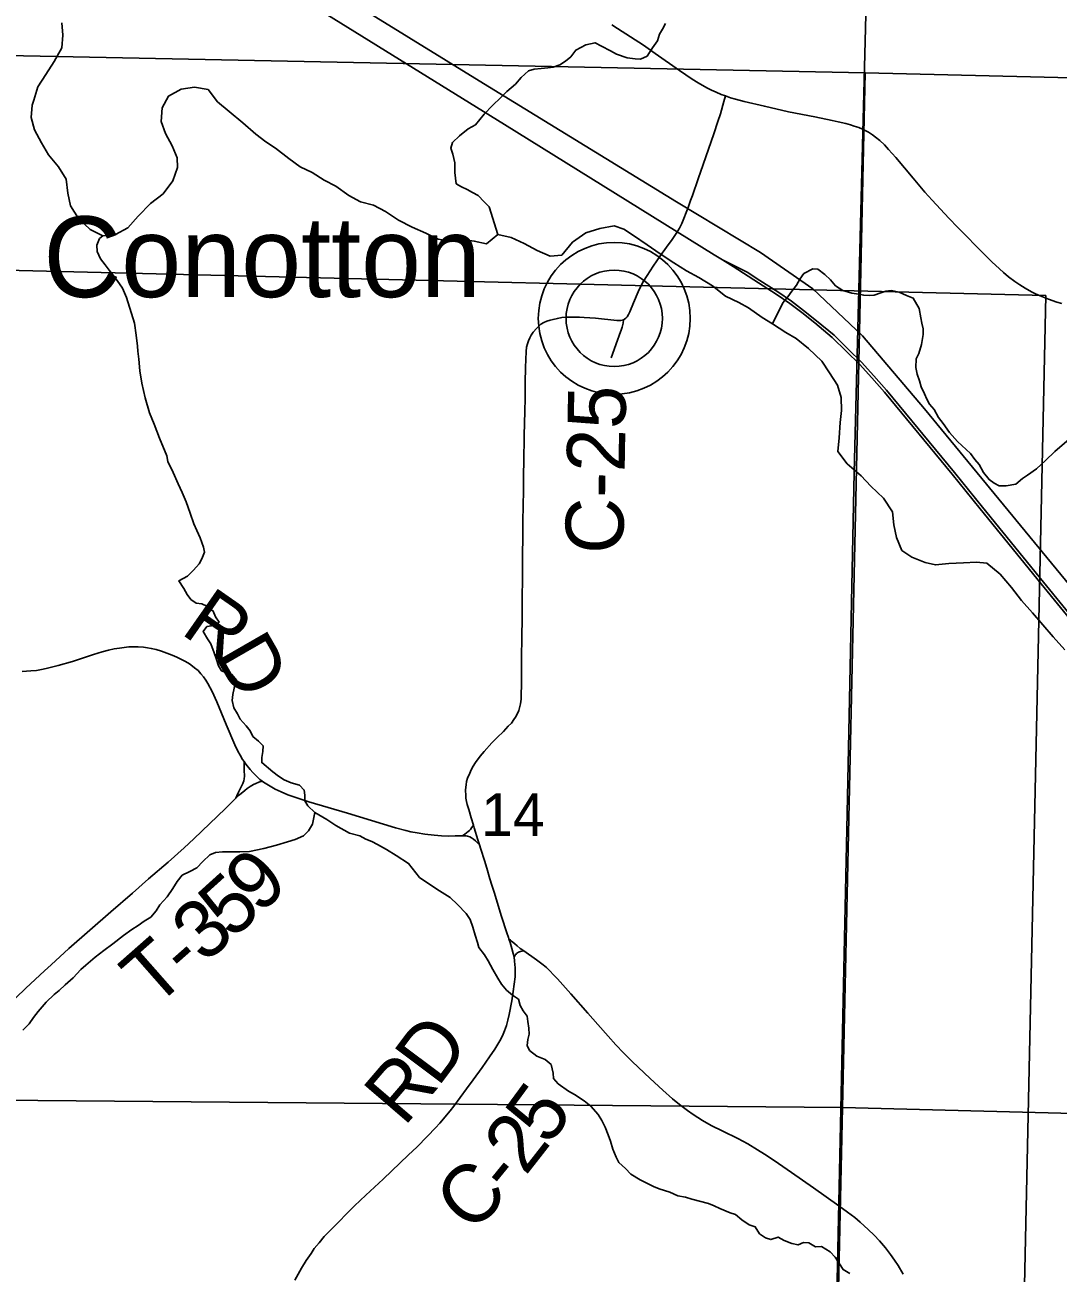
# Model space of a CAD drawing. Extents: x -19.9 to 41.9, y 0 to 32.3.
# Drawn here: x 7.065 to 8.077, y 15.733 to 16.956 of the extents above; entities that cross this region are included whole.
import ezdxf

# ---------------------------------------------------------------- set-up
doc = ezdxf.new("R2010")
doc.units = 0
for name, color, linetype in [('GM_X_Corporation', 7, 'Continuous'), ('GM_X_County_Road', 7, 'Continuous'), ('GM_X_County_Road_Text', 7, 'Continuous'), ('GM_X_Major_River', 7, 'Continuous'), ('GM_X_Minor_River', 7, 'Continuous'), ('GM_X_Rail_Line', 7, 'Continuous'), ('GM_X_Section', 7, 'Continuous'), ('GM_X_Section_Text', 7, 'Continuous'), ('GM_X_State_Route', 7, 'Continuous'), ('GM_X_Township_Road', 7, 'Continuous'), ('GM_X_Township_Road_Text', 7, 'Continuous'), ('GM_X_Unincorporated', 7, 'Continuous'), ('GM_X_Unincorporated_Location', 7, 'Continuous'), ('GM_X_Unincorporated_Text', 7, 'Continuous')]:
    doc.layers.add(name, color=color, linetype=linetype)

msp = doc.modelspace()

# ---------------------------------------------------------------- linework, layer by layer
at = {"layer": 'GM_X_Corporation'}
msp.add_lwpolyline([(2.1, 17.918), (2.1, 14.1), (7.8246, 14.1), (7.8518, 15.3043), (7.854, 15.4058), (7.8702, 16.1679), (7.8776, 16.5173), (7.9012, 17.4524), (7.9072, 17.9171)], dxfattribs=at)
for points in [[(7.8246, 14.1), (8.9, 14.1), (8.9, 17.8974), (7.9072, 17.9171), (7.9012, 17.4524), (7.8776, 16.5173), (7.8702, 16.1679), (7.854, 15.4058), (7.8518, 15.3043)], [(6.8696, 16.9292), (7.8883, 16.9088), (7.8659, 15.8953), (6.8522, 15.9041)], [(8.9, 16.5515), (8.9, 16.8843), (7.8883, 16.9088), (7.8659, 15.8953), (8.8854, 15.8688)], [(7.8659, 15.8953), (7.8436, 14.8739), (6.8226, 14.894), (6.8522, 15.9041)], [(8.8854, 15.8688), (8.8595, 14.8618), (7.8436, 14.8739), (7.8659, 15.8953)]]:
    msp.add_lwpolyline(points, close=True, dxfattribs=at)
at = {"layer": 'GM_X_County_Road'}
for points in [[(7.7173, 16.7836), (7.719, 16.7884), (7.7247, 16.8048), (7.7297, 16.8188), (7.74, 16.8488), (7.7441, 16.861), (7.7466, 16.8685), (7.7498, 16.8807), (7.7513, 16.886)], [(7.5105, 16.1524), (7.5089, 16.1575), (7.5054, 16.169), (7.5046, 16.1716), (7.5023, 16.179), (7.5, 16.1871), (7.4985, 16.1921), (7.4978, 16.1948), (7.4972, 16.1982), (7.4971, 16.2005), (7.4968, 16.2063), (7.4973, 16.2114), (7.4979, 16.2146), (7.4989, 16.2178), (7.5009, 16.2227), (7.5024, 16.2261), (7.5043, 16.2296), (7.5066, 16.2332), (7.511, 16.2392), (7.5152, 16.2438), (7.5226, 16.2524), (7.5278, 16.2575), (7.534, 16.2636), (7.5387, 16.2686), (7.5417, 16.2718), (7.5442, 16.2751), (7.5458, 16.2775), (7.5475, 16.2805), (7.549, 16.2841), (7.5497, 16.2866), (7.5507, 16.2907), (7.5512, 16.2953), (7.5514, 16.3011), (7.5516, 16.3078), (7.5517, 16.3378), (7.5519, 16.3537), (7.552, 16.3602), (7.5522, 16.3704), (7.5523, 16.381), (7.5524, 16.3921), (7.5525, 16.4157), (7.5526, 16.4238), (7.5527, 16.4358), (7.5529, 16.4544), (7.553, 16.467), (7.5533, 16.4873), (7.5535, 16.4969), (7.5537, 16.5158), (7.5538, 16.5273), (7.5542, 16.5536), (7.5548, 16.5772), (7.5551, 16.5896), (7.5553, 16.6055), (7.5556, 16.6199), (7.5561, 16.6357), (7.5566, 16.6401), (7.5575, 16.6433), (7.5585, 16.6463), (7.5597, 16.6491), (7.5612, 16.6516), (7.5632, 16.6546), (7.5662, 16.6582), (7.5682, 16.6603), (7.5707, 16.6624), (7.5736, 16.6641), (7.5764, 16.6654), (7.5796, 16.6663), (7.5826, 16.6672), (7.5868, 16.6682), (7.5911, 16.6689), (7.5961, 16.6695), (7.6086, 16.6693), (7.6131, 16.6691), (7.6241, 16.6683), (7.645, 16.666), (7.6491, 16.6661), (7.6515, 16.6668), (7.6525, 16.6674), (7.6537, 16.6683), (7.6551, 16.6697), (7.6565, 16.6719), (7.6579, 16.6746), (7.6614, 16.6833), (7.666, 16.6942), (7.669, 16.7005), (7.6713, 16.7047), (7.6747, 16.7103), (7.6777, 16.7149), (7.6806, 16.7193), (7.6879, 16.7297), (7.6936, 16.7378), (7.6992, 16.7453), (7.7032, 16.7512), (7.7064, 16.7564), (7.7088, 16.7611), (7.7108, 16.7659), (7.7153, 16.7779), (7.7173, 16.7836)], [(7.0624, 16.3223), (7.0667, 16.3225), (7.0712, 16.3228), (7.0766, 16.3233), (7.0814, 16.3242), (7.0861, 16.3253), (7.0978, 16.3281), (7.1119, 16.3321), (7.1324, 16.3388), (7.141, 16.3415), (7.1472, 16.3431), (7.1526, 16.3444), (7.158, 16.3452), (7.1625, 16.3459), (7.1672, 16.3463), (7.1718, 16.3466), (7.1762, 16.3464), (7.1815, 16.346), (7.1853, 16.3454), (7.189, 16.3449), (7.1937, 16.3437), (7.1991, 16.3421), (7.2044, 16.3402), (7.2096, 16.3383), (7.2141, 16.3363), (7.2181, 16.3343), (7.2225, 16.3322), (7.2265, 16.3298), (7.2295, 16.3276), (7.2315, 16.3259), (7.2348, 16.3231), (7.2376, 16.3201), (7.2401, 16.3171), (7.2424, 16.3138), (7.2444, 16.3105), (7.2487, 16.3026), (7.2532, 16.2927), (7.2625, 16.2705), (7.271, 16.2504), (7.2738, 16.2444), (7.276, 16.2402), (7.2785, 16.2361), (7.28, 16.2341), (7.2818, 16.2315), (7.2859, 16.2263), (7.2884, 16.2234), (7.292, 16.2196), (7.2954, 16.2166), (7.2976, 16.2149), (7.2988, 16.214), (7.3005, 16.2128), (7.3056, 16.2098), (7.3105, 16.2069), (7.3162, 16.2043), (7.3227, 16.2016), (7.3295, 16.1992), (7.3434, 16.1947), (7.3812, 16.1835), (7.4166, 16.1727), (7.4281, 16.1692), (7.4383, 16.1665), (7.4434, 16.1653), (7.4495, 16.1642), (7.457, 16.163), (7.4662, 16.1619), (7.4733, 16.1613), (7.4805, 16.1611), (7.4866, 16.1612), (7.4913, 16.1613), (7.4938, 16.1614)], [(7.4938, 16.1614), (7.4962, 16.163), (7.4979, 16.1642), (7.4994, 16.1654), (7.5008, 16.1666), (7.5016, 16.1675), (7.5028, 16.169), (7.504, 16.1707), (7.5046, 16.1716)], [(7.4938, 16.1614), (7.4975, 16.1612), (7.4989, 16.161), (7.501, 16.1603), (7.5027, 16.1595), (7.5047, 16.1582), (7.5065, 16.1565), (7.5085, 16.1545), (7.5105, 16.1524)], [(7.5392, 16.0604), (7.5388, 16.0616), (7.5372, 16.0663), (7.532, 16.0822), (7.5248, 16.106), (7.5225, 16.1131), (7.5207, 16.1192), (7.5176, 16.1297), (7.5153, 16.137), (7.5118, 16.1484), (7.5105, 16.1524)], [(7.3295, 15.7261), (7.3361, 15.7377), (7.3406, 15.7452), (7.3457, 15.7523), (7.3487, 15.757), (7.3535, 15.7628), (7.3585, 15.7687), (7.3646, 15.7752), (7.3721, 15.7827), (7.381, 15.7916), (7.3882, 15.7989), (7.3991, 15.8094), (7.416, 15.8251), (7.441, 15.8488), (7.4491, 15.8562), (7.4597, 15.867), (7.4674, 15.8752), (7.4716, 15.8798), (7.4818, 15.8921), (7.4853, 15.8966), (7.4979, 15.9135), (7.5044, 15.9224), (7.5131, 15.9344), (7.5204, 15.9448), (7.5256, 15.9525), (7.5296, 15.9589), (7.5313, 15.962), (7.5337, 15.967), (7.5351, 15.9704), (7.5369, 15.9754), (7.5384, 15.9806), (7.5397, 15.9864), (7.5422, 15.9998), (7.5436, 16.0088), (7.5455, 16.0233), (7.5456, 16.026), (7.5454, 16.0321), (7.5448, 16.0386), (7.5443, 16.0427), (7.5436, 16.0461), (7.5423, 16.0509), (7.5405, 16.0568), (7.5392, 16.0604)], [(7.5392, 16.0604), (7.5408, 16.0591), (7.542, 16.0581), (7.5433, 16.057), (7.545, 16.0556), (7.5473, 16.0537), (7.5505, 16.0511), (7.554, 16.0486), (7.5663, 16.04), (7.5691, 16.038), (7.5728, 16.0351), (7.5762, 16.0322), (7.5793, 16.0292), (7.5831, 16.0253), (7.5869, 16.0212), (7.5999, 16.0064), (7.6166, 15.9876), (7.6263, 15.9766), (7.6365, 15.965), (7.6441, 15.9566), (7.6514, 15.9488), (7.66, 15.9403), (7.6658, 15.9347), (7.6776, 15.9237), (7.6902, 15.9122), (7.6997, 15.9038), (7.7064, 15.8982), (7.7141, 15.8923), (7.7199, 15.8882), (7.7288, 15.8825), (7.7374, 15.8777), (7.749, 15.872), (7.7635, 15.8648), (7.7732, 15.8595), (7.7828, 15.8538), (7.7895, 15.8494), (7.7992, 15.8432), (7.816, 15.8315), (7.8377, 15.8165), (7.8625, 15.799), (7.8711, 15.7928), (7.8782, 15.7874), (7.8835, 15.7828), (7.8873, 15.7794), (7.8912, 15.7758), (7.897, 15.77), (7.9023, 15.7645), (7.9081, 15.7577), (7.9132, 15.7513), (7.9171, 15.7456), (7.9207, 15.7403), (7.9256, 15.7321)], [(7.5443, 16.0427), (7.5453, 16.0443), (7.546, 16.0452), (7.5468, 16.046), (7.5477, 16.0467), (7.5486, 16.0472), (7.5496, 16.0476), (7.5507, 16.048), (7.554, 16.0486)]]:
    msp.add_lwpolyline(points, dxfattribs=at)
at = {"layer": 'GM_X_Major_River'}
for points in [[(7.1014, 16.9578), (7.1023, 16.9457), (7.1013, 16.9332), (7.0939, 16.9198), (7.0857, 16.9072), (7.0779, 16.8949), (7.0739, 16.882)], [(7.0739, 16.882), (7.0724, 16.877), (7.0714, 16.8649), (7.0746, 16.8528), (7.0816, 16.84), (7.0882, 16.8283), (7.0982, 16.8166), (7.1055, 16.8046), (7.1072, 16.7909), (7.11, 16.7785), (7.1178, 16.766), (7.1293, 16.7552), (7.1415, 16.7489), (7.1541, 16.7502), (7.1661, 16.7568), (7.1762, 16.7683), (7.1882, 16.7806), (7.2007, 16.7902), (7.21, 16.8028), (7.2148, 16.8158), (7.2143, 16.8253), (7.2096, 16.8373), (7.203, 16.8494), (7.1987, 16.8611), (7.1996, 16.8744), (7.206, 16.8859), (7.2184, 16.8928), (7.2313, 16.8945), (7.2446, 16.8924), (7.2539, 16.8804), (7.2654, 16.8707), (7.2788, 16.8598), (7.2915, 16.8486), (7.3011, 16.8411), (7.3106, 16.8348), (7.3237, 16.8247), (7.3348, 16.8165), (7.3466, 16.8109), (7.3585, 16.8035), (7.3699, 16.7976), (7.3826, 16.7886), (7.394, 16.7823), (7.4066, 16.779), (7.4185, 16.7727), (7.4311, 16.7645), (7.4445, 16.7575), (7.4578, 16.7516), (7.4701, 16.7457), (7.4826, 16.7436), (7.4959, 16.7452), (7.5054, 16.7438), (7.5172, 16.7413), (7.5285, 16.7502), (7.5414, 16.7473), (7.5544, 16.7414), (7.567, 16.7347), (7.5796, 16.7292), (7.591, 16.7301), (7.6015, 16.7427), (7.6147, 16.752), (7.6283, 16.7563), (7.6423, 16.7588), (7.6518, 16.7555), (7.6614, 16.7492), (7.6748, 16.7402), (7.6874, 16.7313), (7.7008, 16.7227), (7.7131, 16.7149), (7.7253, 16.7082), (7.7387, 16.7), (7.7514, 16.6899), (7.7644, 16.6837), (7.7739, 16.6785), (7.7873, 16.6691), (7.7976, 16.6628), (7.8107, 16.6543), (7.8206, 16.6483), (7.8329, 16.6386), (7.8459, 16.6262), (7.8533, 16.6149), (7.861, 16.6029), (7.8646, 16.5908), (7.8651, 16.5779), (7.8638, 16.5661), (7.8628, 16.5513), (7.8615, 16.5377), (7.8707, 16.5256), (7.8842, 16.514), (7.8938, 16.5039), (7.9061, 16.4919), (7.915, 16.4788), (7.9163, 16.4659), (7.9191, 16.4534), (7.9242, 16.4409), (7.9341, 16.4342), (7.9471, 16.4291), (7.957, 16.4266), (7.9703, 16.4282), (7.9847, 16.4288), (7.9972, 16.4293), (8.0075, 16.4283)], [(8.0075, 16.4283), (8.0205, 16.4175), (8.0317, 16.4047), (8.0414, 16.3919), (8.0521, 16.3796), (8.0622, 16.3679), (8.0725, 16.3563), (8.0837, 16.3435)]]:
    msp.add_lwpolyline(points, dxfattribs=at)
at = {"layer": 'GM_X_Minor_River'}
for points in [[(7.5285, 16.7502), (7.52, 16.7773), (7.515, 16.7822), (7.5092, 16.7886), (7.5035, 16.7915), (7.4985, 16.7945), (7.4928, 16.7971), (7.4878, 16.8001), (7.4865, 16.8111), (7.4864, 16.8206), (7.4844, 16.8289), (7.4824, 16.835), (7.4842, 16.8404), (7.4909, 16.8469), (7.4995, 16.8539), (7.5067, 16.8578), (7.5152, 16.8683), (7.5231, 16.8767), (7.5313, 16.8845), (7.5373, 16.8903), (7.5459, 16.8977), (7.5514, 16.9042), (7.5585, 16.9108), (7.5642, 16.9124), (7.571, 16.9129), (7.5774, 16.9137), (7.5827, 16.9142), (7.5891, 16.9166), (7.5948, 16.9201), (7.6, 16.9244), (7.6048, 16.9309), (7.6146, 16.936), (7.6237, 16.9381), (7.6301, 16.9347), (7.6389, 16.9303), (7.6446, 16.927), (7.6553, 16.9233), (7.6629, 16.9223), (7.6682, 16.922), (7.6746, 16.9251), (7.6801, 16.9332), (7.685, 16.9401), (7.6868, 16.9466), (7.6897, 16.9516), (7.6927, 16.957)], [(7.1415, 16.7489), (7.1384, 16.7464), (7.1358, 16.7399), (7.1359, 16.7338), (7.1394, 16.7266), (7.1437, 16.7206), (7.1479, 16.7153), (7.1556, 16.7052), (7.1607, 16.6976), (7.1646, 16.6886), (7.1725, 16.6635), (7.1742, 16.6518), (7.1755, 16.6411), (7.1759, 16.6362), (7.1768, 16.6282), (7.1777, 16.6168), (7.1798, 16.6046), (7.183, 16.5902), (7.1874, 16.5758), (7.1917, 16.5645), (7.1972, 16.5508), (7.2043, 16.5334), (7.2051, 16.5281), (7.2106, 16.5172), (7.2153, 16.5062), (7.2192, 16.4975), (7.2231, 16.4884), (7.2271, 16.4774), (7.2306, 16.4668), (7.2338, 16.4604), (7.2369, 16.4532), (7.2401, 16.4441), (7.2413, 16.4392), (7.2387, 16.4327), (7.2358, 16.4277), (7.2305, 16.4215), (7.2246, 16.4157), (7.2159, 16.411), (7.221, 16.4035), (7.2241, 16.3978), (7.2279, 16.3929), (7.2329, 16.3892), (7.2386, 16.3885), (7.2435, 16.3863), (7.2497, 16.3815), (7.252, 16.3758), (7.2555, 16.3705), (7.2503, 16.3674), (7.2435, 16.3665), (7.2397, 16.3615), (7.244, 16.3543), (7.2475, 16.3495), (7.2506, 16.3407), (7.253, 16.3339), (7.255, 16.3279), (7.2577, 16.323), (7.2627, 16.3211), (7.268, 16.3193), (7.2726, 16.3137), (7.2701, 16.306), (7.269, 16.2999), (7.2684, 16.2938), (7.27, 16.2866), (7.2735, 16.2809), (7.2762, 16.2757), (7.282, 16.2689), (7.2858, 16.264), (7.2886, 16.2587), (7.2939, 16.2542), (7.2985, 16.2494), (7.2982, 16.244), (7.2972, 16.2379), (7.2973, 16.233), (7.308, 16.224), (7.3137, 16.2199), (7.3191, 16.2162), (7.3259, 16.2132), (7.3343, 16.2111), (7.3389, 16.2062), (7.3394, 16.2012), (7.3394, 16.1955), (7.3425, 16.1906), (7.3491, 16.1843), (7.3609, 16.1772), (7.3697, 16.1713), (7.3831, 16.1638), (7.3933, 16.1613), (7.3991, 16.158), (7.4051, 16.1558), (7.4105, 16.1528), (7.4193, 16.148), (7.4288, 16.1421), (7.441, 16.1343), (7.4519, 16.1204), (7.4599, 16.1148), (7.4714, 16.1073), (7.4817, 16.101), (7.489, 16.0939), (7.4974, 16.0853), (7.5013, 16.0792), (7.5041, 16.0717)], [(7.7976, 16.6628), (7.8075, 16.6835), (7.8124, 16.6893), (7.8165, 16.6947), (7.8209, 16.7008), (7.8242, 16.7066), (7.8283, 16.712), (7.837, 16.7167), (7.8419, 16.7164), (7.8488, 16.7111), (7.8542, 16.7059), (7.8592, 16.7002), (7.8664, 16.6954), (7.8752, 16.6929), (7.882, 16.6918), (7.8869, 16.6908), (7.8923, 16.6905), (7.8972, 16.6909), (7.9036, 16.6933), (7.9085, 16.6949), (7.9138, 16.6954), (7.9214, 16.694), (7.9286, 16.6906), (7.9354, 16.6881), (7.9413, 16.6779), (7.9429, 16.6688), (7.9438, 16.6635), (7.945, 16.6578), (7.9451, 16.6524), (7.9433, 16.6425), (7.9408, 16.6337), (7.9382, 16.6284), (7.9379, 16.62), (7.9392, 16.6135), (7.9415, 16.6071), (7.9431, 16.601), (7.9463, 16.5942), (7.9486, 16.5889), (7.9513, 16.584), (7.956, 16.5788), (7.9602, 16.5712), (7.9645, 16.5652), (7.971, 16.5565), (7.9788, 16.5475), (7.9914, 16.5359), (7.9957, 16.5299), (7.9999, 16.525), (8.0042, 16.5171), (8.0096, 16.5103), (8.0146, 16.5066), (8.0195, 16.504), (8.0263, 16.5041), (8.0358, 16.5057), (8.0425, 16.5112), (8.0474, 16.5147), (8.056, 16.5209), (8.065, 16.529), (8.0739, 16.5379), (8.0881, 16.5499)], [(7.3492, 16.1842), (7.347, 16.1728), (7.3429, 16.1663), (7.3381, 16.1613), (7.3298, 16.1577), (7.3226, 16.1553), (7.3117, 16.1521), (7.2992, 16.1489), (7.2853, 16.146), (7.2758, 16.1455), (7.2663, 16.1457), (7.2588, 16.1456), (7.252, 16.1451), (7.2463, 16.1427), (7.2396, 16.1362), (7.2336, 16.13), (7.2269, 16.1264), (7.2193, 16.1229), (7.2145, 16.1167), (7.2101, 16.1098), (7.2045, 16.1014), (7.1974, 16.0936), (7.1937, 16.0879), (7.1885, 16.0817), (7.1821, 16.0778), (7.1761, 16.0735), (7.1701, 16.0696), (7.1619, 16.0638), (7.1514, 16.0556), (7.1424, 16.049), (7.1342, 16.0424), (7.1248, 16.0347), (7.12, 16.0304), (7.1125, 16.0223), (7.1047, 16.0153), (7.0987, 16.0099), (7.0938, 16.006), (7.086, 15.9983), (7.0782, 15.9891), (7.0737, 15.9833), (7.0693, 15.9771), (7.0633, 15.9709)], [(7.5041, 16.0717), (7.5064, 16.0641), (7.5084, 16.0569), (7.51, 16.052), (7.5154, 16.0448), (7.5189, 16.0388), (7.5236, 16.0305), (7.5286, 16.0218), (7.5321, 16.0161), (7.5371, 16.0101), (7.5429, 16.0053), (7.5486, 16.0012), (7.5502, 15.9951), (7.5533, 15.9898), (7.5572, 15.9846), (7.558, 15.9796), (7.5589, 15.9728), (7.5593, 15.9671), (7.5579, 15.9617), (7.5572, 15.956), (7.5596, 15.9511), (7.5668, 15.9455), (7.5748, 15.9422), (7.5806, 15.9373), (7.5826, 15.929), (7.5831, 15.9237), (7.5877, 15.9184), (7.5976, 15.9113), (7.6037, 15.908), (7.6129, 15.9017), (7.6194, 15.8964), (7.6267, 15.8882), (7.6302, 15.8825), (7.6337, 15.8761), (7.6365, 15.8685), (7.6389, 15.8621), (7.6412, 15.8545), (7.6444, 15.8466), (7.6471, 15.8413), (7.6536, 15.8353), (7.6586, 15.83), (7.6678, 15.8245), (7.6808, 15.8178), (7.6865, 15.8156), (7.6968, 15.8124), (7.7048, 15.8087), (7.7124, 15.8073), (7.7184, 15.8055), (7.7348, 15.8011), (7.7405, 15.7989), (7.7458, 15.7964), (7.7561, 15.7919), (7.7614, 15.7905), (7.7676, 15.7853), (7.7745, 15.7804), (7.7806, 15.7782), (7.7848, 15.7715), (7.7905, 15.7677), (7.7959, 15.7659), (7.803, 15.7683), (7.8088, 15.765), (7.8164, 15.762), (7.8225, 15.7606), (7.8277, 15.763), (7.833, 15.7627), (7.8395, 15.7586), (7.8456, 15.7591), (7.854, 15.7539), (7.859, 15.7486), (7.8667, 15.7365), (7.8732, 15.7325)]]:
    msp.add_lwpolyline(points, dxfattribs=at)
at = {"layer": 'GM_X_Rail_Line'}
for points in [[(8.1483, 16.3345), (7.9464, 16.5797), (7.8856, 16.651), (7.837, 16.6972), (7.7859, 16.7327), (7.7034, 16.7822), (7.5103, 16.9007), (7.3078, 17.0259)], [(7.2854, 17.0128), (7.5349, 16.858), (7.7404, 16.7305), (7.7486, 16.7255), (7.7728, 16.7135), (7.7852, 16.7054), (7.8026, 16.6942), (7.8162, 16.6849), (7.8279, 16.676), (7.8406, 16.6659), (7.8579, 16.6516), (7.872, 16.6378), (7.8848, 16.6252), (7.8968, 16.6118), (7.9093, 16.5977), (7.9757, 16.5173), (8.0031, 16.4834), (8.0629, 16.4099), (8.1226, 16.3367)], [(7.7486, 16.7255), (7.7591, 16.7191), (7.7837, 16.703), (7.801, 16.6918), (7.8145, 16.6827), (7.8262, 16.6738), (7.8388, 16.6637), (7.856, 16.6495), (7.87, 16.6357), (7.8828, 16.6233), (7.8947, 16.6099), (7.9071, 16.5959), (7.9735, 16.5155), (8.0008, 16.4816), (8.0607, 16.4081), (8.1204, 16.3349)]]:
    msp.add_lwpolyline(points, dxfattribs=at)
at = {"layer": 'GM_X_Section'}
msp.add_lwpolyline([(8.0651, 16.6907), (8.0435, 15.6754), (7.0239, 15.7019), (7.0463, 16.7153)], close=True, dxfattribs=at)
at = {"layer": 'GM_X_State_Route'}
msp.add_lwpolyline([(7.6402, 16.9558), (7.6458, 16.9521), (7.6711, 16.9357), (7.6826, 16.9277), (7.7063, 16.9111), (7.7188, 16.9026), (7.7246, 16.8989), (7.7331, 16.894), (7.7376, 16.8917), (7.7422, 16.8896), (7.7471, 16.8876), (7.7513, 16.886), (7.7563, 16.8843), (7.7613, 16.8828), (7.7697, 16.8806), (7.7896, 16.8759), (7.8131, 16.8705), (7.8388, 16.8655), (7.8559, 16.8621), (7.8619, 16.8607), (7.8694, 16.859), (7.8738, 16.8578), (7.8776, 16.8566), (7.8819, 16.855), (7.8857, 16.8534), (7.8914, 16.8505), (7.8956, 16.8479), (7.8984, 16.8457), (7.9027, 16.8425), (7.9072, 16.8381), (7.9112, 16.8337), (7.9182, 16.8257), (7.9353, 16.8054), (7.9466, 16.7919), (7.9539, 16.7838), (7.9703, 16.7663), (7.9789, 16.7573), (8.0055, 16.7304), (8.0123, 16.7237), (8.0197, 16.7166), (8.0237, 16.7132), (8.0287, 16.709), (8.0348, 16.7044), (8.0398, 16.701), (8.0451, 16.6977), (8.0513, 16.6942), (8.0552, 16.6923), (8.0614, 16.6895), (8.0677, 16.687), (8.076, 16.6842), (8.0809, 16.6827)], dxfattribs=at)
at = {"layer": 'GM_X_Township_Road'}
for points in [[(7.6473, 16.6513), (7.6496, 16.6576), (7.6502, 16.6597), (7.6511, 16.6636), (7.6515, 16.6668)], [(7.6395, 16.6294), (7.6457, 16.6468), (7.6473, 16.6513)], [(7.2719, 16.1982), (7.2727, 16.2005), (7.2745, 16.204), (7.2762, 16.2074), (7.2778, 16.2106), (7.2787, 16.2127), (7.2797, 16.2151), (7.2801, 16.217), (7.2804, 16.2199), (7.2801, 16.2256), (7.2799, 16.2292), (7.28, 16.2341)], [(7.0564, 16.0026), (7.0663, 16.012), (7.0754, 16.0207), (7.0843, 16.0291), (7.0909, 16.0351), (7.1083, 16.0508), (7.1288, 16.0688), (7.1495, 16.0868), (7.1706, 16.1053), (7.1863, 16.1193), (7.2056, 16.1355), (7.2211, 16.1494), (7.2307, 16.1584), (7.2616, 16.188), (7.2719, 16.1982), (7.2746, 16.2009), (7.277, 16.2029), (7.2806, 16.2058), (7.2831, 16.2078), (7.2859, 16.2097), (7.2891, 16.2116), (7.2913, 16.2127), (7.2943, 16.2139), (7.2976, 16.2149)]]:
    msp.add_lwpolyline(points, dxfattribs=at)
at = {"layer": 'GM_X_Unincorporated'}
for radius in [0.0744, 0.0472]:
    msp.add_circle((7.6425, 16.6682), radius, dxfattribs=at)
at = {"layer": 'GM_X_Unincorporated_Location'}
msp.add_line((7.6425, 16.6682), (7.6425, 16.6682), dxfattribs=at)

# ---------------------------------------------------------------- texts
at = {"layer": 'GM_X_County_Road_Text'}
for s, height, rotation, p in [('C-25', 0.05682, 88.9662, (7.6512, 16.4371)), ('R', 0.0568, 325.0953, (7.2165, 16.3602)), ('D', 0.0568, 299.931, (7.2503, 16.3383)), ('D', 0.0568, 53.1804, (7.4696, 15.9141)), ('R', 0.0568, 49.3233, (7.4366, 15.8755)), ('5', 0.0568, 53.6791, (7.5781, 15.8566)), ('2', 0.0568, 51.9858, (7.5555, 15.8275)), ('C', 0.0568, 44.448, (7.5019, 15.7707)), ('-', 0.0568, 50.7452, (7.5399, 15.8084))]:
    msp.add_text(s, height=height, rotation=rotation, dxfattribs=at).set_placement(p)
at = {"layer": 'GM_X_Section_Text'}
msp.add_text('14', height=0.04186, rotation=0, dxfattribs=at).set_placement((7.5121, 16.1611))
at = {"layer": 'GM_X_Township_Road_Text'}
for s, rotation, p in [('9', 43.5523, (7.2951, 16.0835)), ('5', 42.0841, (7.268, 16.059)), ('3', 41.6112, (7.2414, 16.0354)), ('T', 41.3641, (7.1918, 15.9917)), ('-', 41.4024, (7.2238, 16.0198))]:
    msp.add_text(s, height=0.0568, rotation=rotation, dxfattribs=at).set_placement(p)
at = {"layer": 'GM_X_Unincorporated_Text'}
msp.add_text('Conotton', height=0.07898, rotation=0, dxfattribs=at).set_placement((7.0833, 16.689))

doc.saveas('drawing.dxf')
